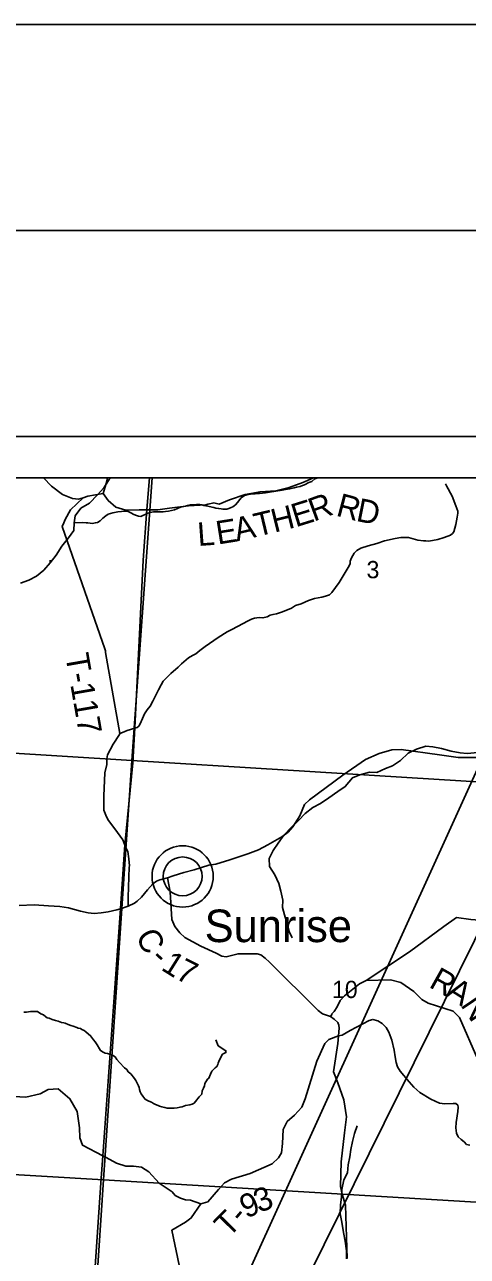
# Model space of a CAD drawing. Extents: x 0 to 45.4, y -2.2 to 22.
# Drawn here: x 5.991 to 7.067, y 19.01 to 22 of the extents above; entities that cross this region are included whole.
import ezdxf

# ---------------------------------------------------------------- set-up
doc = ezdxf.new("R2010")
doc.units = 0
for name, color, linetype in [('GM_X_Corporation', 7, 'Continuous'), ('GM_X_County_Road', 7, 'Continuous'), ('GM_X_County_Road_Text', 7, 'Continuous'), ('GM_X_Minor_River', 7, 'Continuous'), ('GM_X_Section_Text', 7, 'Continuous'), ('GM_X_State_Route', 7, 'Continuous'), ('GM_X_Township_Road', 7, 'Continuous'), ('GM_X_Township_Road_Text', 7, 'Continuous'), ('GM_X_Unincorporated', 7, 'Continuous'), ('GM_X_Unincorporated_Location', 7, 'Continuous'), ('GM_X_Unincorporated_Text', 7, 'Continuous'), ('SH_Border', 7, 'Continuous'), ('SH_Cut_Line', 7, 'Continuous'), ('SH_Data', 7, 'Continuous'), ('SH_Text', 7, 'Continuous')]:
    doc.layers.add(name, color=color, linetype=linetype)

msp = doc.modelspace()

# ---------------------------------------------------------------- linework, layer by layer
at = {"layer": 'GM_X_Corporation'}
for points in [[(5.6021, 14.1), (7.0413, 14.1), (7.1146, 14.1136), (7.5608, 14.2194), (7.6244, 14.2444), (8.0832, 14.3972), (8.4711, 14.5406), (8.5907, 14.5823), (8.8228, 14.6772), (8.9, 14.7192), (8.9, 20.9), (2.1, 20.9)], [(5.642, 18.1908), (6.1061, 18.1607), (6.1763, 19.1885), (6.181, 19.2539), (6.2236, 19.8542), (6.2346, 20.0088), (6.2538, 20.2076), (6.2588, 20.2929), (6.2789, 20.7002), (6.2882, 20.8226), (6.2942, 20.9), (2.1, 20.9)], [(5.6021, 14.1), (7.0413, 14.1), (7.1146, 14.1136), (7.5608, 14.2194), (7.6244, 14.2444), (8.0832, 14.3972), (8.4711, 14.5406), (8.5907, 14.5823), (8.8228, 14.6772), (8.9, 14.7192), (8.9, 20.9), (6.2942, 20.9), (6.2882, 20.8226), (6.2789, 20.7002), (6.2588, 20.2929), (6.2538, 20.2076), (6.2346, 20.0088), (6.2236, 19.8542), (6.181, 19.2539), (6.1763, 19.1885), (6.1061, 18.1607), (5.642, 18.1908)]]:
    msp.add_lwpolyline(points, dxfattribs=at)
for points in [[(6.3012, 20.9), (5.1793, 20.9), (5.1309, 20.2827), (6.2516, 20.2138)], [(7.4048, 20.9), (6.3012, 20.9), (6.2516, 20.2138), (7.3518, 20.1452)], [(5.1309, 20.2827), (6.2516, 20.2138), (6.1827, 19.1954), (5.073, 19.2613)], [(6.2516, 20.2138), (7.3518, 20.1452), (7.2905, 19.1287), (6.1827, 19.1954)], [(6.1827, 19.1954), (6.1142, 18.166), (5.0121, 18.2353), (5.073, 19.2613)], [(7.2905, 19.1287), (7.2262, 18.1039), (6.1142, 18.166), (6.1827, 19.1954)]]:
    msp.add_lwpolyline(points, close=True, dxfattribs=at)
at = {"layer": 'GM_X_County_Road'}
for points in [[(6.0368, 20.9), (6.0561, 20.8795), (6.0827, 20.8593), (6.107, 20.8495), (6.1221, 20.8479), (6.133, 20.8514)], [(6.4367, 20.8358), (6.4503, 20.8387), (6.464, 20.836), (6.489, 20.8463), (6.5267, 20.8592), (6.5631, 20.866), (6.6011, 20.8683), (6.6338, 20.8766), (6.6668, 20.8887), (6.6908, 20.8986), (6.694, 20.9)], [(6.133, 20.8514), (6.1446, 20.8551), (6.1818, 20.8616)], [(6.1818, 20.8616), (6.1939, 20.8449), (6.2129, 20.8282), (6.2372, 20.8209), (6.2691, 20.8221), (6.2884, 20.8221), (6.3063, 20.8221)], [(6.3063, 20.8221), (6.3143, 20.8221), (6.3432, 20.8258), (6.3888, 20.8315), (6.4309, 20.8345), (6.4358, 20.8356), (6.4367, 20.8358)], [(6.3382, 19.9289), (6.3444, 19.8943), (6.3488, 19.8271), (6.3561, 19.8104), (6.3681, 19.7954), (6.3805, 19.7834), (6.4194, 19.7629), (6.4566, 19.7457), (6.4701, 19.7385), (6.4805, 19.7371), (6.5095, 19.7445), (6.539, 19.7445), (6.5561, 19.7441), (6.5651, 19.7415), (6.575, 19.7338), (6.5858, 19.7241), (6.7041, 19.6063), (6.7146, 19.5984), (6.734, 19.5919), (6.737, 19.5972)], [(6.737, 19.5972), (6.7375, 19.5981), (6.7434, 19.6045), (6.7503, 19.6158), (6.758, 19.6307), (6.7678, 19.6423), (6.8042, 19.6713), (6.8207, 19.6792), (6.8797, 19.6811), (6.905, 19.6747), (6.9367, 19.6526), (6.9557, 19.6336), (6.9716, 19.6241), (7.0318, 19.6051), (7.0476, 19.5892), (7.092, 19.4879)], [(6.7746, 19.0042), (6.7705, 19.1341), (6.7623, 19.1609), (6.7581, 19.1795), (6.7602, 19.2393), (6.7685, 19.3094), (6.7726, 19.3486), (6.7664, 19.3899), (6.752, 19.4311), (6.7417, 19.4579), (6.7516, 19.5268), (6.7532, 19.545), (6.7552, 19.564), (6.7542, 19.5712), (6.7516, 19.5771), (6.7434, 19.5853), (6.734, 19.5919)]]:
    msp.add_lwpolyline(points, dxfattribs=at)
at = {"layer": 'GM_X_Minor_River'}
for points in [[(6.0526, 20.6931), (6.0679, 20.7122), (6.0816, 20.7341), (6.0975, 20.7538), (6.1105, 20.772), (6.1113, 20.7902), (6.1136, 20.8076), (6.1273, 20.8258), (6.1485, 20.8379), (6.1683, 20.8583), (6.1835, 20.8757), (6.1949, 20.8931), (6.1986, 20.9)], [(6.1113, 20.7902), (6.1317, 20.7915), (6.1408, 20.7902), (6.1449, 20.7901), (6.1498, 20.7896), (6.1555, 20.7892), (6.1624, 20.7902), (6.1684, 20.7916), (6.1742, 20.7957), (6.1807, 20.802), (6.188, 20.8076), (6.1938, 20.8117), (6.1995, 20.8135), (6.2052, 20.8145), (6.2174, 20.817), (6.2261, 20.818), (6.2329, 20.8186), (6.2371, 20.8185), (6.2424, 20.8177), (6.2492, 20.8149), (6.2563, 20.811), (6.2627, 20.8082), (6.2679, 20.8063), (6.2729, 20.8062), (6.2778, 20.808), (6.2836, 20.8109), (6.2904, 20.8142), (6.2958, 20.8153), (6.3041, 20.817), (6.3147, 20.8176), (6.3227, 20.8175), (6.3272, 20.8174), (6.3329, 20.8181), (6.3405, 20.8187), (6.355, 20.8223), (6.3626, 20.8252), (6.3698, 20.8285), (6.3816, 20.8313), (6.3866, 20.8324), (6.3934, 20.8338), (6.4002, 20.8344), (6.4086, 20.835), (6.4165, 20.8349), (6.4211, 20.834), (6.4267, 20.8328), (6.4362, 20.8308), (6.4464, 20.8283), (6.4505, 20.8279), (6.4554, 20.8262), (6.4626, 20.825), (6.4686, 20.8241), (6.4728, 20.8237), (6.4777, 20.8236), (6.4819, 20.8239), (6.4868, 20.8253), (6.4925, 20.8275), (6.4971, 20.829), (6.5029, 20.8342), (6.5079, 20.8402), (6.5137, 20.8469), (6.5172, 20.8514), (6.5253, 20.857), (6.5344, 20.8595), (6.5458, 20.8612), (6.5511, 20.8611), (6.5575, 20.8617), (6.5617, 20.862), (6.5685, 20.8627), (6.5761, 20.8633), (6.586, 20.865), (6.5966, 20.8668), (6.6016, 20.8674), (6.6115, 20.8692), (6.6168, 20.8702), (6.6289, 20.8719), (6.6346, 20.873), (6.646, 20.8754), (6.6514, 20.8769), (6.6605, 20.879), (6.6662, 20.8808), (6.6712, 20.883), (6.6811, 20.8885), (6.6887, 20.8906), (6.6964, 20.897), (6.7006, 20.8988), (6.7023, 20.9)], [(6.0526, 20.6931), (6.0526, 20.6999)], [(5.9812, 20.644), (6.0009, 20.6515), (6.0199, 20.6613), (6.0374, 20.6757), (6.0526, 20.6931)], [(7.092, 20.2331), (7.0663, 20.2302), (7.0488, 20.2325), (7.0269, 20.2364), (7.0034, 20.2426), (6.983, 20.2464), (6.9656, 20.248), (6.9429, 20.2413)], [(6.9429, 20.2413), (6.9231, 20.2315), (6.9041, 20.2133), (6.8851, 20.2005), (6.8677, 20.1937), (6.8464, 20.1847), (6.829, 20.1848), (6.8055, 20.1788), (6.7873, 20.1712), (6.7698, 20.1501), (6.7523, 20.138), (6.7303, 20.1229), (6.7098, 20.1093), (6.6908, 20.0995), (6.6726, 20.0851), (6.6566, 20.0677), (6.6391, 20.0518), (6.6209, 20.0322), (6.6071, 20.0125), (6.5949, 19.9951), (6.585, 19.9754), (6.5857, 19.9564), (6.5985, 19.9358), (6.6082, 19.9146), (6.6135, 19.8963), (6.6179, 19.8743), (6.6178, 19.8568), (6.6223, 19.8386), (6.629, 19.8173), (6.6335, 19.7983), (6.641, 19.7831)], [(5.9888, 19.6027), (5.9952, 19.6029), (6.0055, 19.6039), (6.0153, 19.6045), (6.0221, 19.6044), (6.0304, 19.5985), (6.0368, 19.5958), (6.0424, 19.5915), (6.0461, 19.5888), (6.0506, 19.5876), (6.0581, 19.5848), (6.0661, 19.5824), (6.0725, 19.5804), (6.0807, 19.5776), (6.086, 19.5764), (6.0898, 19.5755), (6.0966, 19.5724), (6.1033, 19.5704), (6.1086, 19.5688), (6.1176, 19.5652), (6.1214, 19.564), (6.1263, 19.5628), (6.1297, 19.5601), (6.1353, 19.5581), (6.1398, 19.5546), (6.1458, 19.5491), (6.151, 19.5453), (6.1584, 19.5353), (6.1621, 19.5303)], [(6.1621, 19.5303), (6.1673, 19.523), (6.1732, 19.5138), (6.1754, 19.5092), (6.1821, 19.5052), (6.1863, 19.5033), (6.1923, 19.502), (6.1968, 19.5008), (6.2043, 19.4984), (6.2107, 19.4938), (6.2151, 19.4876), (6.2218, 19.4807), (6.2337, 19.4675), (6.239, 19.4637), (6.2426, 19.4579), (6.2486, 19.4532), (6.2579, 19.4417), (6.2612, 19.4367), (6.2674, 19.4237), (6.2689, 19.4199), (6.2699, 19.4145), (6.2713, 19.4088), (6.2739, 19.4046), (6.278, 19.3985), (6.2828, 19.3919), (6.2865, 19.39), (6.2925, 19.3864), (6.2993, 19.3837), (6.3038, 19.3809), (6.3087, 19.3782), (6.3151, 19.3758), (6.3184, 19.3746), (6.3241, 19.373), (6.3279, 19.3718), (6.3313, 19.371), (6.3369, 19.3697), (6.349, 19.3695), (6.354, 19.3698), (6.3619, 19.3705), (6.3688, 19.3719), (6.3737, 19.3725), (6.3821, 19.3758), (6.3924, 19.3775), (6.3984, 19.379), (6.4027, 19.3819), (6.4065, 19.386), (6.4147, 19.3969), (6.4212, 19.4033), (6.4225, 19.4112), (6.4253, 19.418), (6.4276, 19.4233), (6.4285, 19.429), (6.4351, 19.4395), (6.4389, 19.4421), (6.4425, 19.4519), (6.4457, 19.459), (6.4538, 19.4673), (6.458, 19.4706), (6.46, 19.4755), (6.4608, 19.4789), (6.4636, 19.4849), (6.4718, 19.5004), (6.4802, 19.5044), (6.4799, 19.509), (6.4612, 19.5211), (6.4558, 19.5356)], [(6.7733, 19.0038), (6.7726, 19.0227), (6.7697, 19.0463), (6.766, 19.0676), (6.7616, 19.0926), (6.7579, 19.1131), (6.7587, 19.1351), (6.761, 19.1534), (6.7619, 19.1716), (6.7665, 19.1951), (6.7757, 19.2125), (6.7773, 19.2315), (6.7812, 19.2512), (6.7835, 19.2694), (6.7874, 19.2884), (6.7928, 19.3081), (6.7989, 19.3263)]]:
    msp.add_lwpolyline(points, dxfattribs=at)
at = {"layer": 'GM_X_State_Route'}
for points in [[(6.2427, 19.8601), (6.2579, 19.8672), (6.2645, 19.8721), (6.2752, 19.8819), (6.2891, 19.8994), (6.3028, 19.9142), (6.3113, 19.9206), (6.3196, 19.9238), (6.3382, 19.9289), (6.3521, 19.9336), (6.378, 19.9413), (6.4026, 19.9482), (6.4386, 19.9592), (6.4553, 19.9618), (6.4895, 19.972), (6.5334, 19.9871), (6.5589, 19.9967), (6.5815, 20.0084), (6.6155, 20.0278), (6.6314, 20.0396), (6.6426, 20.0524), (6.6594, 20.0791), (6.6706, 20.1065), (6.6833, 20.1183), (6.7641, 20.1775), (6.8195, 20.2156), (6.8524, 20.2303), (6.8835, 20.239), (6.9055, 20.24), (6.9986, 20.2273), (7.044, 20.2207), (7.0977, 20.2206)], [(5.9778, 19.8613), (6.0143, 19.8628), (6.0489, 19.8609), (6.0763, 19.8593), (6.0978, 19.8555), (6.1271, 19.8474), (6.1453, 19.8437), (6.1596, 19.8418), (6.1773, 19.8434), (6.1937, 19.8461), (6.2149, 19.8507), (6.2238, 19.8537), (6.2427, 19.8601)]]:
    msp.add_lwpolyline(points, dxfattribs=at)
at = {"layer": 'GM_X_Township_Road'}
for points in [[(6.1818, 20.8616), (6.1887, 20.8863), (6.1927, 20.9)], [(6.9656, 20.7467), (6.9734, 20.7461), (6.9946, 20.7503), (7.0104, 20.7546), (7.0257, 20.7608), (7.0308, 20.7647), (7.0339, 20.769), (7.0387, 20.7868), (7.0418, 20.8041), (7.0432, 20.8142), (7.0432, 20.819), (7.039, 20.8318), (7.0296, 20.855), (7.0254, 20.8623), (7.0197, 20.8733), (7.0158, 20.8807), (7.0135, 20.8849)], [(6.0858, 20.7905), (6.0891, 20.7986), (6.1028, 20.8217), (6.133, 20.8514)], [(6.133, 20.8514), (6.1446, 20.8551), (6.1818, 20.8616)], [(6.1871, 20.4798), (6.1862, 20.4845), (6.0822, 20.7815), (6.0858, 20.7905)], [(6.3721, 20.4482), (6.3775, 20.4534), (6.3894, 20.4627), (6.3987, 20.4681), (6.4069, 20.4721), (6.4163, 20.4808), (6.4295, 20.4902), (6.4615, 20.5119), (6.4833, 20.5258), (6.4943, 20.5314), (6.5217, 20.5462), (6.5322, 20.5515), (6.5424, 20.5569), (6.5495, 20.5589), (6.5608, 20.5603), (6.5698, 20.5597), (6.58, 20.5626), (6.5876, 20.566), (6.5944, 20.5676), (6.6026, 20.5696), (6.6173, 20.5741), (6.6394, 20.5832), (6.6487, 20.5894), (6.6626, 20.5942), (6.6804, 20.6021), (6.6951, 20.6064), (6.7129, 20.6098), (6.7222, 20.6126), (6.729, 20.6146), (6.7318, 20.6157), (6.7375, 20.6211), (6.755, 20.6457), (6.7774, 20.6819), (6.7816, 20.6907), (6.7822, 20.6972), (6.7853, 20.7054), (6.7915, 20.717), (6.7977, 20.7232), (6.8079, 20.7291), (6.8255, 20.7348), (6.8464, 20.7407), (6.8656, 20.7464), (6.8913, 20.7523), (6.9046, 20.7546), (6.9168, 20.7551), (6.9233, 20.7546), (6.9349, 20.7515), (6.9462, 20.7483), (6.9598, 20.7472), (6.9656, 20.7467)], [(6.2224, 20.2792), (6.1877, 20.4761), (6.1871, 20.4798)], [(6.2224, 20.2792), (6.2286, 20.2815), (6.2402, 20.2863), (6.2591, 20.2924), (6.2641, 20.294), (6.2684, 20.297), (6.2713, 20.3028), (6.277, 20.3154), (6.2818, 20.3266), (6.2884, 20.3365), (6.2962, 20.3455), (6.3022, 20.3578), (6.3098, 20.3724), (6.3164, 20.3848), (6.3227, 20.3975), (6.3277, 20.4058), (6.3362, 20.4152), (6.3464, 20.4248), (6.3639, 20.4404), (6.3721, 20.4482)], [(6.2453, 19.9548), (6.2454, 19.9576), (6.2445, 19.9745), (6.2413, 19.9923), (6.2379, 20.0003), (6.2348, 20.0083), (6.2299, 20.021), (6.2164, 20.0387), (6.1932, 20.0701), (6.1879, 20.0811), (6.1834, 20.0929), (6.183, 20.128), (6.1859, 20.1834), (6.1908, 20.2038), (6.1908, 20.2176), (6.1926, 20.2274), (6.2062, 20.2531), (6.2211, 20.2764), (6.2224, 20.2792)], [(6.8207, 19.6792), (6.9258, 19.7487), (7.0094, 19.8102), (7.0402, 19.8322), (7.0754, 19.8278), (7.1281, 19.8234), (7.1501, 19.8366), (7.2029, 19.863), (7.2161, 19.8806), (7.2029, 19.9025), (7.1677, 19.9421), (7.1589, 19.9597), (7.1809, 19.9773), (7.2205, 19.9949), (7.2381, 20.0037), (7.2645, 20.0168), (7.2865, 20.0124), (7.3216, 19.9993), (7.3304, 19.9993), (7.3832, 20.008), (7.48, 20.096), (7.4954, 20.1127), (7.4987, 20.1162)], [(6.2427, 19.8601), (6.2423, 19.8817), (6.2453, 19.9548)], [(7.0728, 19.2795), (7.0646, 19.2813), (7.059, 19.2875), (7.0514, 19.2936), (7.0439, 19.2999), (7.0401, 19.3087), (7.0385, 19.3215), (7.0391, 19.3347), (7.0431, 19.361), (7.0439, 19.372), (7.0431, 19.3771), (7.0388, 19.3805), (7.0321, 19.381), (7.0122, 19.3797), (6.999, 19.3813), (6.978, 19.391), (6.9509, 19.4076), (6.9363, 19.4204), (6.9251, 19.4331), (6.9031, 19.4594), (6.897, 19.4699), (6.8933, 19.4803), (6.8912, 19.4937), (6.8889, 19.5104), (6.8828, 19.5342), (6.8761, 19.5537), (6.8692, 19.5655), (6.8597, 19.575), (6.8489, 19.5817), (6.8373, 19.5848), (6.8281, 19.5825), (6.813, 19.5743), (6.7822, 19.5583), (6.7621, 19.5465), (6.7532, 19.545)], [(6.3914, 19.0999), (6.3958, 19.1031), (6.4191, 19.1373), (6.4363, 19.1419), (6.4621, 19.1718), (6.4765, 19.1885), (6.4935, 19.1969), (6.5386, 19.2109), (6.592, 19.2344), (6.608, 19.2492), (6.6152, 19.2613), (6.6178, 19.2834), (6.6193, 19.3179), (6.6292, 19.3369), (6.6466, 19.3528), (6.6644, 19.3722), (6.6724, 19.3919), (6.7012, 19.4837), (6.7201, 19.5266), (6.73, 19.5361), (6.7532, 19.545)], [(5.9644, 19.3974), (5.9936, 19.3963), (6.0288, 19.4042), (6.0485, 19.4148), (6.0724, 19.4164), (6.1008, 19.3924), (6.1186, 19.3617), (6.1243, 19.3218), (6.125, 19.2972), (6.1314, 19.2793), (6.1812, 19.2534), (6.1891, 19.2493)], [(6.1891, 19.2493), (6.2144, 19.236), (6.2371, 19.2284), (6.2557, 19.2288), (6.2746, 19.2265), (6.2928, 19.2151), (6.3182, 19.1874), (6.3492, 19.1665), (6.3568, 19.1578), (6.3693, 19.1506), (6.3818, 19.1472), (6.3943, 19.1457), (6.4191, 19.1373)], [(6.4474, 18.5435), (6.4457, 18.5649), (6.448, 18.5979), (6.3487, 19.0736), (6.3818, 19.0929), (6.3914, 19.0999)]]:
    msp.add_lwpolyline(points, dxfattribs=at)
at = {"layer": 'GM_X_Unincorporated'}
for radius in [0.0744, 0.0472]:
    msp.add_circle((6.3749, 19.9321), radius, dxfattribs=at)
at = {"layer": 'GM_X_Unincorporated_Location'}
msp.add_line((6.3749, 19.9321), (6.3749, 19.9321), dxfattribs=at)
at = {"layer": 'SH_Border'}
msp.add_lwpolyline([(1.5, 21.5), (33.5, 21.5), (33.5, 0.5), (1.5, 0.5)], close=True, dxfattribs=at)
at = {"layer": 'SH_Cut_Line'}
msp.add_lwpolyline([(0, 0), (34, 0), (34, 22), (0, 22)], close=True, dxfattribs=at)
at = {"layer": 'SH_Data'}
for p, q in [((2, 21), (9, 21)), ((2.1, 20.9), (8.9, 20.9))]:
    msp.add_line(p, q, dxfattribs=at)
at = {"layer": 'SH_Text'}
msp.add_lwpolyline([(7.4129, 20.9), (4.8173, 15.1976), (7.4129, 20.4406)], close=True, dxfattribs=at)

# ---------------------------------------------------------------- texts
at = {"layer": 'GM_X_County_Road_Text'}
for s, rotation, p in [('E', 17.2273, (6.6495, 20.7794)), ('R', 20.1681, (6.6932, 20.793)), ('R', 345.1591, (6.7454, 20.8083)), ('D', 348.6519, (6.7942, 20.7954)), ('T', 13.5202, (6.5558, 20.7565)), ('H', 13.8438, (6.5975, 20.7665)), ('L', 4.0597, (6.4126, 20.7341)), ('E', 9.0258, (6.4603, 20.7377)), ('A', 12.8793, (6.5064, 20.7451)), ('C', 298.2217, (6.2592, 19.7869)), ('-', 316.97, (6.2936, 19.7298)), ('1', 327.8251, (6.32, 19.7067)), ('7', 333.1217, (6.3546, 19.6853)), ('R', 330.78, (6.9709, 19.6646)), ('A', 327.6869, (7.0109, 19.6423)), ('N', 304.025, (7.0488, 19.6198))]:
    msp.add_text(s, height=0.0568, rotation=rotation, dxfattribs=at).set_placement(p)
at = {"layer": 'GM_X_Section_Text'}
for s, height, p in [('3', 0.0419, (6.8217, 20.656)), ('10', 0.04186, (6.7379, 19.6368))]:
    msp.add_text(s, height=height, rotation=0, dxfattribs=at).set_placement(p)
at = {"layer": 'GM_X_Township_Road_Text'}
for s, height, rotation, p in [('T-117', 0.05682, 279.8778, (6.0895, 20.469)), ('3', 0.0568, 21.212, (6.5607, 19.1147)), ('9', 0.0568, 24.0758, (6.5294, 19.1007)), ('T', 0.0568, 45.45, (6.4868, 19.0533)), ('-', 0.0568, 49.6189, (6.5196, 19.0869))]:
    msp.add_text(s, height=height, rotation=rotation, dxfattribs=at).set_placement(p)
at = {"layer": 'GM_X_Unincorporated_Text'}
msp.add_text('Sunrise', height=0.07898, rotation=0, dxfattribs=at).set_placement((6.4283, 19.7726))

doc.saveas('drawing.dxf')
